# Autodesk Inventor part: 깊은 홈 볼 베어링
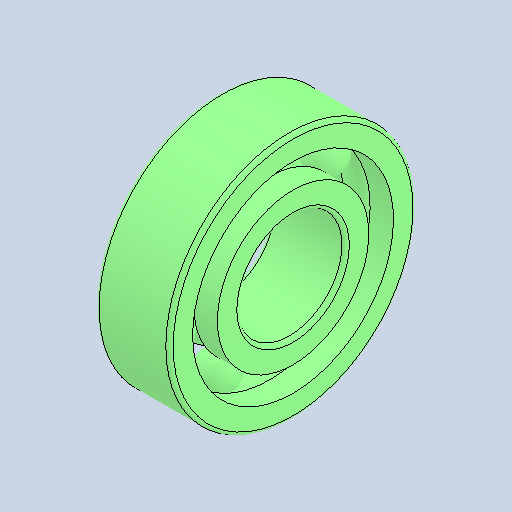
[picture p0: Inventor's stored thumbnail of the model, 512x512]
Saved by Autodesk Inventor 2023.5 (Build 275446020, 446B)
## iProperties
Created: 2026-07
Part Number: 깊은 홈 볼 베어링
Material: 강철, 연강
Description: 깊은 그루브 볼 베어링
Document SubType Name: Modeling
Designer: mirae
Density: 7.86 g/cm^3
Appearance: 기본값
Author: jhkim
Revision Number: 1
Sending System: Autodesk Inventor 2027
Preprocessor: ST-DEVELOPER v20.1
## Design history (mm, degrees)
node "깊은 홈 볼 베어링 62031"
node "솔리드1"
node "솔리드2"
node "솔리드3"
node "솔리드4"
node "솔리드5"
node "솔리드6"
node "솔리드7"
node "솔리드8"
node "솔리드9"
body "Solid1"
node "Solid1:1"
node "Solid1:2"
node "Solid1:3"
node "Solid1:4"
node "Solid1:5"
node "Solid1:6"
node "Solid1:7"
node "Solid1:8"
